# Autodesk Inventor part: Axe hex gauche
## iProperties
Author: Flavien MARTY
Shininess: 60.0
PropertySet Name: _Private Model Information
Created: 2001-10
Part Number: Axe hex gauche
Material: Par défaut
Document SubType Name: Modélisation
Designer: Flavien MARTY
Control State: 0
Master: False
Checked Out: False
PropertySet Name: Design Tracking Control
Density: 0.0
Volumn: 0.0
Area: 0.0
PropertySet Name: Model Information
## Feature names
1. Base1
